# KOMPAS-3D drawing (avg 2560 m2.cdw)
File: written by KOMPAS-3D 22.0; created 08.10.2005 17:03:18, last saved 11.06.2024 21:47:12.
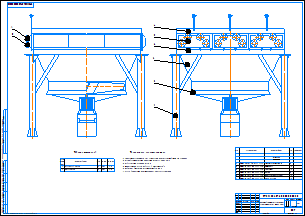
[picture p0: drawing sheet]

Sheet 1: A1, landscape

Document properties: Наименование: Аппарат воздушного охлаждения горизонтального типа (АВГ) / Чертеж общего вида; Полное имя файла: I:\Учёба\Курсовое проектирование\Курсовой проект 4 курс\ИЗО Л-35-5 УНХ\ИЗО диплом\АВГ\avg 2560 m2.cdw

Title block, sheet 1: Наименование: Аппарат воздушного охлаждения / горизонтального типа (АВГ); designation: УТЭК.18.02.09.ДП.00.00.000.ВО; scale: 1:20; Количество листов документа: 1; organisation: ПНГ; Форматы листов документа: A1; stored path: C:\Documents and Settings\Администратор\Мои документы\Курсовой проект\Чертеж.cdw

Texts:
  Normal
  Поз.
  Кол.
  УТЭК 18.02.09 ДП.00.00.001
  Металлоконструкция
  Детали
  УТЭК 18.02.09 ДП.00.00.002
  Диффузор
  УТЭК 18.02.09 ДП.00.00.003
  Коллектор
  УТЭК 18.02.09 ДП.00.00.004
  Жалюзи
  УТЭК 18.02.09 ДП.00.00.005
  Теплообменная секция
  УТЭК 18.02.09 ДП.00.00.006
  Рамка сборная
  Техническая характеристика
  Аппарат предназначен для охлаждения газопродуктовой смеси бензина
  Производительность аппарата по сырью 13,47 кг/с
  Поверхность секции 2560 м2
  Температура среды на входе в аппарат 105␣С
  Symbol
  Давление в трубном пространстве 4 МПа
  Среда в аппарате малотоксичная, слабокоррозионная
  Таблица штуцеров
  Обоз-
  наче-
  ние
  Dу, мм
  Pу, МПа
  Ввод паров смеси
  Вывод смеси
Dimensions and other numbers on the sheet: 1; 4; 2; 3; 5; 6; 150; 6,4; 1:20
